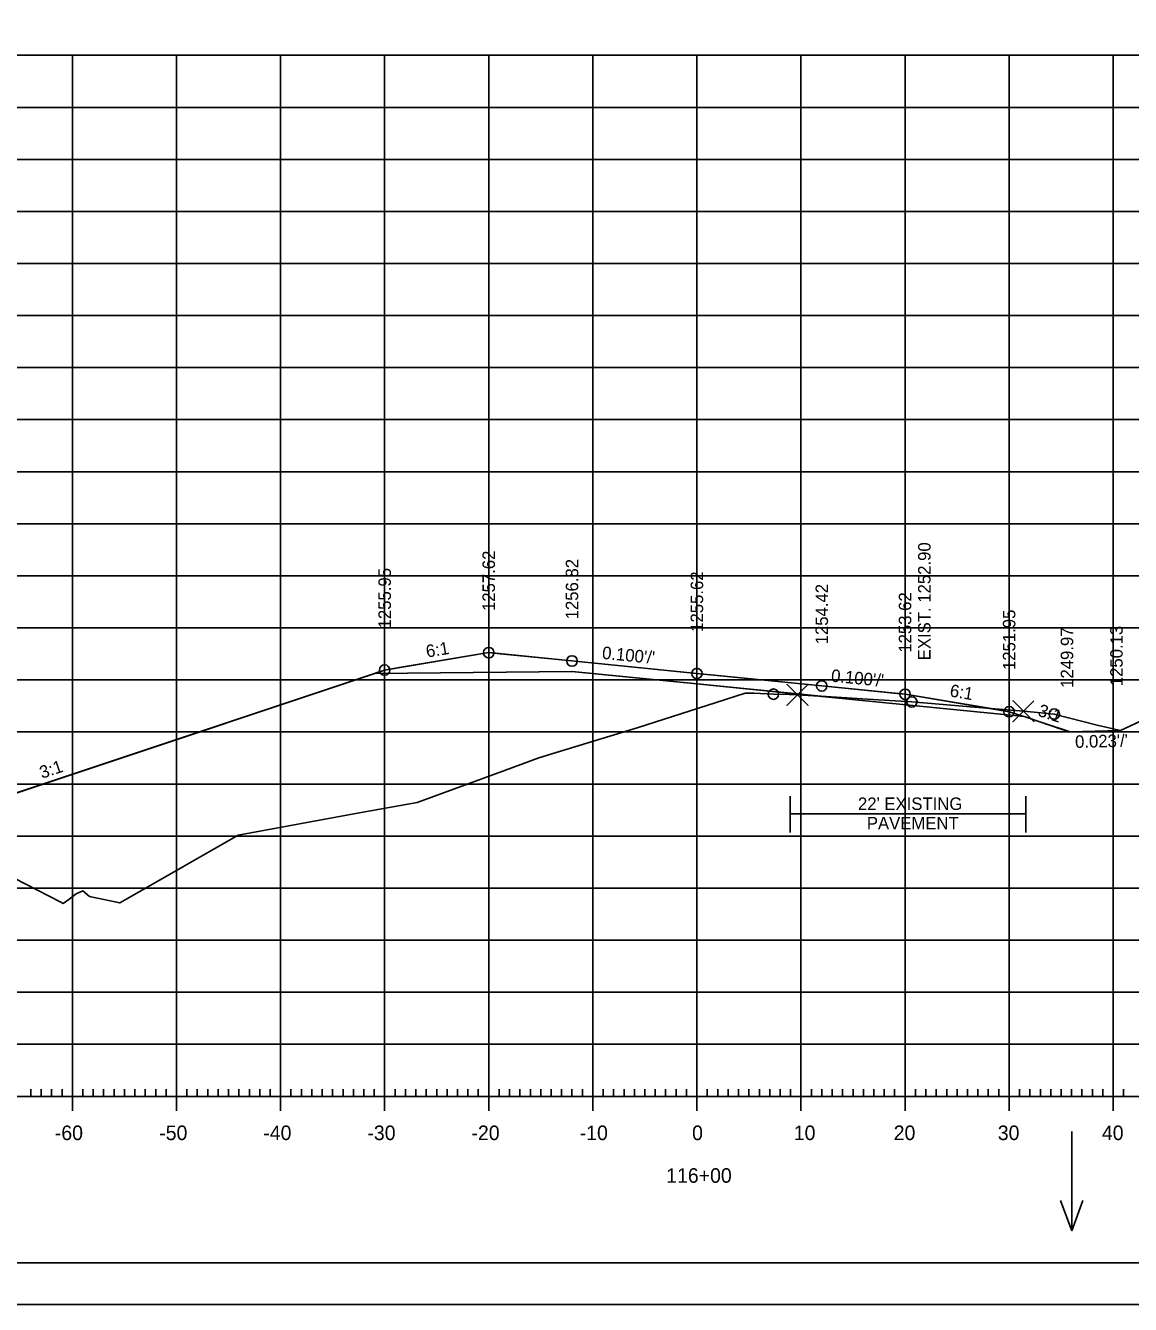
# Model space of a CAD drawing. Extents: x 1406028 to 1412453, y 321733 to 325986.
# Drawn here: x 1406525.4 to 1406631.5, y 324279.4 to 324402.2 of the extents above; entities that cross this region are included whole.
import ezdxf

# ---------------------------------------------------------------- set-up
doc = ezdxf.new("R2010")
doc.units = 0
for name, color, linetype in [('R_Alt Surface', 7, 'Continuous'), ('R_Axis', 7, 'Continuous'), ('R_Axis Annot', 7, 'Continuous'), ('R_Border', 7, 'Continuous'), ('R_Draft', 7, 'Continuous'), ('R_Exist Surface', 7, 'Continuous'), ('R_Fin Surface', 7, 'Continuous'), ('R_Fin Surface Annot', 7, 'Continuous'), ('R_Grid', 7, 'Continuous'), ('R_No Plot', 7, 'Continuous'), ('R_Proposed Road', 7, 'Continuous'), ('R_Water Annot', 7, 'Continuous'), ('R_Xsect Elev', 7, 'Continuous')]:
    doc.layers.add(name, color=color, linetype=linetype)

msp = doc.modelspace()

# ---------------------------------------------------------------- linework, layer by layer
at = {"layer": 'R_Alt Surface'}
msp.add_lwpolyline([(1406558.92, 324340), (1406577.89, 324340.19), (1406589.89, 324338.99), (1406601.89, 324337.79), (1406621.32, 324335.85)], dxfattribs=at)
at = {"layer": 'R_Axis'}
for p, q in [((1406525.89, 324299.37), (1406525.89, 324300.07)), ((1406526.89, 324299.37), (1406526.89, 324300.07)), ((1406527.89, 324299.37), (1406527.89, 324300.07)), ((1406528.89, 324299.37), (1406528.89, 324300.07)), ((1406529.89, 324297.97), (1406529.89, 324300.77)), ((1406530.89, 324299.37), (1406530.89, 324300.07)), ((1406531.89, 324299.37), (1406531.89, 324300.07)), ((1406532.89, 324299.37), (1406532.89, 324300.07)), ((1406533.89, 324299.37), (1406533.89, 324300.07)), ((1406534.89, 324299.37), (1406534.89, 324300.07)), ((1406535.89, 324299.37), (1406535.89, 324300.07)), ((1406536.89, 324299.37), (1406536.89, 324300.07)), ((1406537.89, 324299.37), (1406537.89, 324300.07)), ((1406538.89, 324299.37), (1406538.89, 324300.07)), ((1406539.89, 324297.97), (1406539.89, 324300.77)), ((1406540.89, 324299.37), (1406540.89, 324300.07)), ((1406541.89, 324299.37), (1406541.89, 324300.07)), ((1406542.89, 324299.37), (1406542.89, 324300.07)), ((1406543.89, 324299.37), (1406543.89, 324300.07)), ((1406544.89, 324299.37), (1406544.89, 324300.07)), ((1406545.89, 324299.37), (1406545.89, 324300.07)), ((1406546.89, 324299.37), (1406546.89, 324300.07)), ((1406547.89, 324299.37), (1406547.89, 324300.07)), ((1406548.89, 324299.37), (1406548.89, 324300.07)), ((1406549.89, 324297.97), (1406549.89, 324300.77)), ((1406550.89, 324299.37), (1406550.89, 324300.07)), ((1406551.89, 324299.37), (1406551.89, 324300.07)), ((1406552.89, 324299.37), (1406552.89, 324300.07)), ((1406553.89, 324299.37), (1406553.89, 324300.07)), ((1406554.89, 324299.37), (1406554.89, 324300.07)), ((1406555.89, 324299.37), (1406555.89, 324300.07)), ((1406556.89, 324299.37), (1406556.89, 324300.07)), ((1406557.89, 324299.37), (1406557.89, 324300.07)), ((1406558.89, 324299.37), (1406558.89, 324300.07)), ((1406559.89, 324297.97), (1406559.89, 324300.77)), ((1406560.89, 324299.37), (1406560.89, 324300.07)), ((1406561.89, 324299.37), (1406561.89, 324300.07)), ((1406562.89, 324299.37), (1406562.89, 324300.07)), ((1406563.89, 324299.37), (1406563.89, 324300.07)), ((1406564.89, 324299.37), (1406564.89, 324300.07)), ((1406565.89, 324299.37), (1406565.89, 324300.07)), ((1406566.89, 324299.37), (1406566.89, 324300.07)), ((1406567.89, 324299.37), (1406567.89, 324300.07)), ((1406568.89, 324299.37), (1406568.89, 324300.07)), ((1406569.89, 324297.97), (1406569.89, 324300.77)), ((1406570.89, 324299.37), (1406570.89, 324300.07)), ((1406571.89, 324299.37), (1406571.89, 324300.07)), ((1406572.89, 324299.37), (1406572.89, 324300.07)), ((1406573.89, 324299.37), (1406573.89, 324300.07)), ((1406574.89, 324299.37), (1406574.89, 324300.07)), ((1406575.89, 324299.37), (1406575.89, 324300.07)), ((1406576.89, 324299.37), (1406576.89, 324300.07)), ((1406577.89, 324299.37), (1406577.89, 324300.07)), ((1406578.89, 324299.37), (1406578.89, 324300.07)), ((1406579.89, 324297.97), (1406579.89, 324300.77)), ((1406580.89, 324299.37), (1406580.89, 324300.07)), ((1406581.89, 324299.37), (1406581.89, 324300.07)), ((1406582.89, 324299.37), (1406582.89, 324300.07)), ((1406583.89, 324299.37), (1406583.89, 324300.07)), ((1406584.89, 324299.37), (1406584.89, 324300.07)), ((1406585.89, 324299.37), (1406585.89, 324300.07)), ((1406586.89, 324299.37), (1406586.89, 324300.07)), ((1406587.89, 324299.37), (1406587.89, 324300.07)), ((1406588.89, 324299.37), (1406588.89, 324300.07)), ((1406589.89, 324297.97), (1406589.89, 324300.77)), ((1406590.89, 324299.37), (1406590.89, 324300.07)), ((1406591.89, 324299.37), (1406591.89, 324300.07)), ((1406592.89, 324299.37), (1406592.89, 324300.07)), ((1406593.89, 324299.37), (1406593.89, 324300.07)), ((1406594.89, 324299.37), (1406594.89, 324300.07)), ((1406595.89, 324299.37), (1406595.89, 324300.07)), ((1406596.89, 324299.37), (1406596.89, 324300.07)), ((1406597.89, 324299.37), (1406597.89, 324300.07)), ((1406598.89, 324299.37), (1406598.89, 324300.07)), ((1406599.89, 324297.97), (1406599.89, 324300.77)), ((1406600.89, 324299.37), (1406600.89, 324300.07)), ((1406601.89, 324299.37), (1406601.89, 324300.07)), ((1406602.89, 324299.37), (1406602.89, 324300.07)), ((1406603.89, 324299.37), (1406603.89, 324300.07)), ((1406604.89, 324299.37), (1406604.89, 324300.07)), ((1406605.89, 324299.37), (1406605.89, 324300.07)), ((1406606.89, 324299.37), (1406606.89, 324300.07)), ((1406607.89, 324299.37), (1406607.89, 324300.07)), ((1406608.89, 324299.37), (1406608.89, 324300.07)), ((1406609.89, 324297.97), (1406609.89, 324300.77)), ((1406610.89, 324299.37), (1406610.89, 324300.07)), ((1406611.89, 324299.37), (1406611.89, 324300.07)), ((1406612.89, 324299.37), (1406612.89, 324300.07)), ((1406613.89, 324299.37), (1406613.89, 324300.07)), ((1406614.89, 324299.37), (1406614.89, 324300.07)), ((1406615.89, 324299.37), (1406615.89, 324300.07)), ((1406616.89, 324299.37), (1406616.89, 324300.07)), ((1406617.89, 324299.37), (1406617.89, 324300.07)), ((1406618.89, 324299.37), (1406618.89, 324300.07)), ((1406619.89, 324297.97), (1406619.89, 324300.77)), ((1406620.89, 324299.37), (1406620.89, 324300.07)), ((1406621.89, 324299.37), (1406621.89, 324300.07)), ((1406622.89, 324299.37), (1406622.89, 324300.07)), ((1406623.89, 324299.37), (1406623.89, 324300.07)), ((1406624.89, 324299.37), (1406624.89, 324300.07)), ((1406625.89, 324299.37), (1406625.89, 324300.07)), ((1406626.89, 324299.37), (1406626.89, 324300.07)), ((1406627.89, 324299.37), (1406627.89, 324300.07)), ((1406628.89, 324299.37), (1406628.89, 324300.07)), ((1406629.89, 324297.97), (1406629.89, 324300.77)), ((1406630.89, 324299.37), (1406630.89, 324300.07)), ((1406449.89, 324299.37), (1406729.89, 324299.37))]:
    msp.add_line(p, q, dxfattribs=at)
at = {"layer": 'R_Border'}
msp.add_line((1406748.07, 324283.37), (1406431.89, 324283.37), dxfattribs=at)
at = {"layer": 'R_Draft'}
for p, q in [((1406598.85, 324328.22), (1406598.85, 324324.72)), ((1406621.48, 324328.22), (1406621.48, 324324.72)), ((1406598.87, 324326.51), (1406621.46, 324326.51))]:
    msp.add_line(p, q, dxfattribs=at)
at = {"layer": 'R_Exist Surface'}
msp.add_lwpolyline([(1406522.03, 324321.49), (1406528.77, 324318.04), (1406528.99, 324317.9), (1406529.55, 324318.29), (1406530.24, 324318.84), (1406530.88, 324319.1), (1406531.52, 324318.57), (1406534.44, 324317.95), (1406535.41, 324318.52), (1406545.83, 324324.45), (1406557.62, 324326.63), (1406563.03, 324327.61), (1406571.49, 324330.7), (1406574.72, 324331.89), (1406576.68, 324332.49), (1406584.16, 324334.76), (1406591.73, 324337.2), (1406594.52, 324338.11), (1406595.4, 324338.1), (1406597.24, 324338), (1406598.76, 324337.96), (1406599.55, 324337.94), (1406606.27, 324337.53), (1406610.54, 324337.26), (1406615.79, 324336.82), (1406621.27, 324336.37), (1406622.97, 324336.21), (1406624.23, 324336.09), (1406628.35, 324335.04), (1406630.6, 324334.5), (1406632.99, 324335.62)], dxfattribs=at)
at = {"layer": 'R_Fin Surface'}
for points in [[(1406506.16, 324322.41), (1406558.92, 324340), (1406559.06, 324340.04), (1406559.89, 324340.32), (1406561.28, 324340.55), (1406569.89, 324341.99), (1406571, 324341.88), (1406577.89, 324341.19), (1406588.29, 324340.15), (1406589.89, 324339.99), (1406591.56, 324339.82), (1406601.89, 324338.79), (1406608.81, 324338.1), (1406609.89, 324337.99), (1406618.55, 324336.55), (1406619.89, 324336.32), (1406621.12, 324335.91), (1406621.32, 324335.85), (1406625.09, 324334.59), (1406625.11, 324334.58), (1406625.71, 324334.38), (1406630.6, 324334.5)], [(1406569.89, 324341.99), (1406577.89, 324341.19), (1406589.89, 324339.99), (1406601.89, 324338.79), (1406609.89, 324337.99)]]:
    msp.add_lwpolyline(points, dxfattribs=at)
at = {"layer": 'R_Grid'}
for p, q in [((1406449.89, 324399.37), (1406729.89, 324399.37)), ((1406529.89, 324299.37), (1406529.89, 324399.37)), ((1406539.89, 324299.37), (1406539.89, 324399.37)), ((1406549.89, 324299.37), (1406549.89, 324399.37)), ((1406559.89, 324299.37), (1406559.89, 324399.37)), ((1406569.89, 324299.37), (1406569.89, 324399.37)), ((1406579.89, 324299.37), (1406579.89, 324399.37)), ((1406589.89, 324299.37), (1406589.89, 324399.37)), ((1406599.89, 324299.37), (1406599.89, 324399.37)), ((1406609.89, 324299.37), (1406609.89, 324399.37)), ((1406619.89, 324299.37), (1406619.89, 324399.37)), ((1406629.89, 324299.37), (1406629.89, 324399.37)), ((1406449.89, 324394.37), (1406729.89, 324394.37)), ((1406449.89, 324389.37), (1406729.89, 324389.37)), ((1406449.89, 324384.37), (1406729.89, 324384.37)), ((1406449.89, 324379.37), (1406729.89, 324379.37)), ((1406449.89, 324374.37), (1406729.89, 324374.37)), ((1406449.89, 324369.37), (1406729.89, 324369.37)), ((1406449.89, 324364.37), (1406729.89, 324364.37)), ((1406449.89, 324359.37), (1406729.89, 324359.37)), ((1406449.89, 324354.37), (1406729.89, 324354.37)), ((1406449.89, 324349.37), (1406729.89, 324349.37)), ((1406449.89, 324344.37), (1406729.89, 324344.37)), ((1406449.89, 324339.37), (1406729.89, 324339.37)), ((1406449.89, 324334.37), (1406729.89, 324334.37)), ((1406449.89, 324329.37), (1406729.89, 324329.37)), ((1406449.89, 324324.37), (1406729.89, 324324.37)), ((1406449.89, 324319.37), (1406729.89, 324319.37)), ((1406449.89, 324314.37), (1406729.89, 324314.37)), ((1406449.89, 324309.37), (1406729.89, 324309.37)), ((1406449.89, 324304.37), (1406729.89, 324304.37)), ((1406449.89, 324299.37), (1406729.89, 324299.37))]:
    msp.add_line(p, q, dxfattribs=at)
at = {"layer": 'R_No Plot'}
msp.add_line((1406419.49, 324279.39), (1406752.82, 324279.39), dxfattribs=at)
for points in [[(1406419.48, 324492.72), (1406752.82, 324492.72), (1406752.82, 324279.39), (1406419.48, 324279.39)], [(1406665.81, 324488.83), (1406685.43, 324488.83), (1406685.43, 324478.95), (1406701.54, 324478.95), (1406724.74, 324478.95), (1406724.74, 324454.62), (1406748.07, 324454.62), (1406748.07, 324283.37), (1406431.89, 324283.37), (1406431.89, 324488.83)], [(1406601.79, 324337.8), (1406606.27, 324337.53), (1406610.54, 324337.26), (1406615.79, 324336.82), (1406621.27, 324336.37), (1406622.97, 324336.21), (1406624.23, 324336.09), (1406628.35, 324335.04), (1406630.6, 324334.5), (1406625.75, 324334.37), (1406623.02, 324335.29), (1406621.34, 324335.85), (1406601.91, 324337.79)]]:
    msp.add_lwpolyline(points, close=True, dxfattribs=at)
for points in [[(1406522.03, 324321.49), (1406528.77, 324318.04), (1406528.99, 324317.9), (1406529.55, 324318.29), (1406530.24, 324318.84), (1406530.88, 324319.1), (1406531.52, 324318.57), (1406534.44, 324317.95), (1406535.41, 324318.52), (1406545.83, 324324.45), (1406557.62, 324326.63), (1406563.03, 324327.61), (1406571.49, 324330.7), (1406574.72, 324331.89), (1406576.68, 324332.49), (1406584.16, 324334.76), (1406591.73, 324337.2), (1406594.52, 324338.11), (1406595.4, 324338.1), (1406597.24, 324338), (1406598.76, 324337.96), (1406599.55, 324337.94), (1406601.79, 324337.8), (1406589.91, 324338.99), (1406577.91, 324340.19), (1406558.94, 324340), (1406501.72, 324320.92)], [(1406599.55, 324337.94), (1406598.55, 324338.94), (1406599.55, 324337.94), (1406598.55, 324336.94), (1406599.55, 324337.94), (1406600.55, 324336.94), (1406599.55, 324337.94), (1406600.55, 324338.94)], [(1406621.27, 324336.37), (1406620.27, 324337.37), (1406621.27, 324336.37), (1406620.27, 324335.37), (1406621.27, 324336.37), (1406622.27, 324335.37), (1406621.27, 324336.37), (1406622.27, 324337.37)]]:
    msp.add_lwpolyline(points, dxfattribs=at)
for centre in [(1406569.89, 324341.99), (1406559.89, 324340.32), (1406577.89, 324341.19), (1406589.89, 324339.99), (1406597.24, 324338), (1406601.89, 324338.79), (1406609.89, 324337.99), (1406610.54, 324337.26), (1406619.89, 324336.32), (1406624.23, 324336.09)]:
    msp.add_circle(centre, 0.5, dxfattribs=at)
at = {"layer": 'R_Proposed Road'}
for points in [[(1406569.89, 324341.99), (1406559.89, 324340.32)], [(1406559.89, 324340.32), (1406496.9, 324319.33)], [(1406609.89, 324337.99), (1406619.89, 324336.32)]]:
    msp.add_lwpolyline(points, dxfattribs=at)
at = {"layer": 'R_Water Annot'}
for p, q in [((1406625.9, 324296.01), (1406625.9, 324286.44)), ((1406625.9, 324286.44), (1406624.83, 324289.37)), ((1406625.9, 324286.44), (1406626.97, 324289.37))]:
    msp.add_line(p, q, dxfattribs=at)

# ---------------------------------------------------------------- texts
at = {"layer": 'R_Axis Annot'}
for s, p in [('-60', (1406528.2, 324295.17)), ('-50', (1406538.23, 324295.17)), ('-40', (1406548.23, 324295.17)), ('-30', (1406558.23, 324295.17)), ('-20', (1406568.23, 324295.17)), ('-10', (1406578.63, 324295.17)), ('0', (1406589.43, 324295.17)), ('10', (1406599.2, 324295.17)), ('20', (1406608.8, 324295.17)), ('30', (1406618.8, 324295.17)), ('40', (1406628.8, 324295.17)), ('116+00', (1406586.94, 324291.07))]:
    msp.add_text(s, height=1.4, dxfattribs=at).set_placement(p)
at = {"layer": 'R_Draft'}
for s, p in [("22' EXISTING ", (1406605.37, 324326.88)), ('PAVEMENT', (1406606.22, 324325.01))]:
    msp.add_text(s, height=1.2, dxfattribs=at).set_placement(p)
at = {"layer": 'R_Fin Surface Annot'}
for s, rotation, p in [('1257.62', 90, (1406570.49, 324345.99)), ('1256.82', 90, (1406578.49, 324345.19)), ('1255.95', 90, (1406560.49, 324344.32)), ('1255.62', 90, (1406590.49, 324343.99)), ('1254.42', 90, (1406602.49, 324342.79)), ('1253.62', 90, (1406610.49, 324341.99)), ('1251.95', 90, (1406620.49, 324340.32)), ('1249.97', 90, (1406626.05, 324338.61)), ('1250.13', 90, (1406630.8, 324338.77)), ('6:1', 9.4642, (1406563.96, 324341.51)), ("0.100'/'", 354.2894, (1406580.74, 324341.41)), ("0.100'/'", 354.2894, (1406602.74, 324339.21)), ('6:1', 350.5358, (1406614.13, 324337.79)), ('3:1', 341.5666, (1406622.57, 324335.95)), ("0.023'/'", 1.3398, (1406626.24, 324332.84)), ('3:1', 18.4333, (1406526.97, 324329.87))]:
    msp.add_text(s, height=1.2, rotation=rotation, dxfattribs=at).set_placement(p)
at = {"layer": 'R_No Plot'}
for p in [(1406594.48, 324338.06), (1406584.11, 324334.71), (1406630.55, 324334.45), (1406574.68, 324331.84), (1406562.99, 324327.56), (1406545.79, 324324.4), (1406530.2, 324318.79), (1406528.95, 324317.85), (1406534.4, 324317.9)]:
    msp.add_text('+', height=0.1, dxfattribs=at).set_placement(p)
at = {"layer": 'R_Xsect Elev'}
msp.add_text('EXIST. 1252.90', height=1.2, rotation=90, dxfattribs=at).set_placement((1406612.34, 324341.26))

doc.saveas('drawing.dxf')
